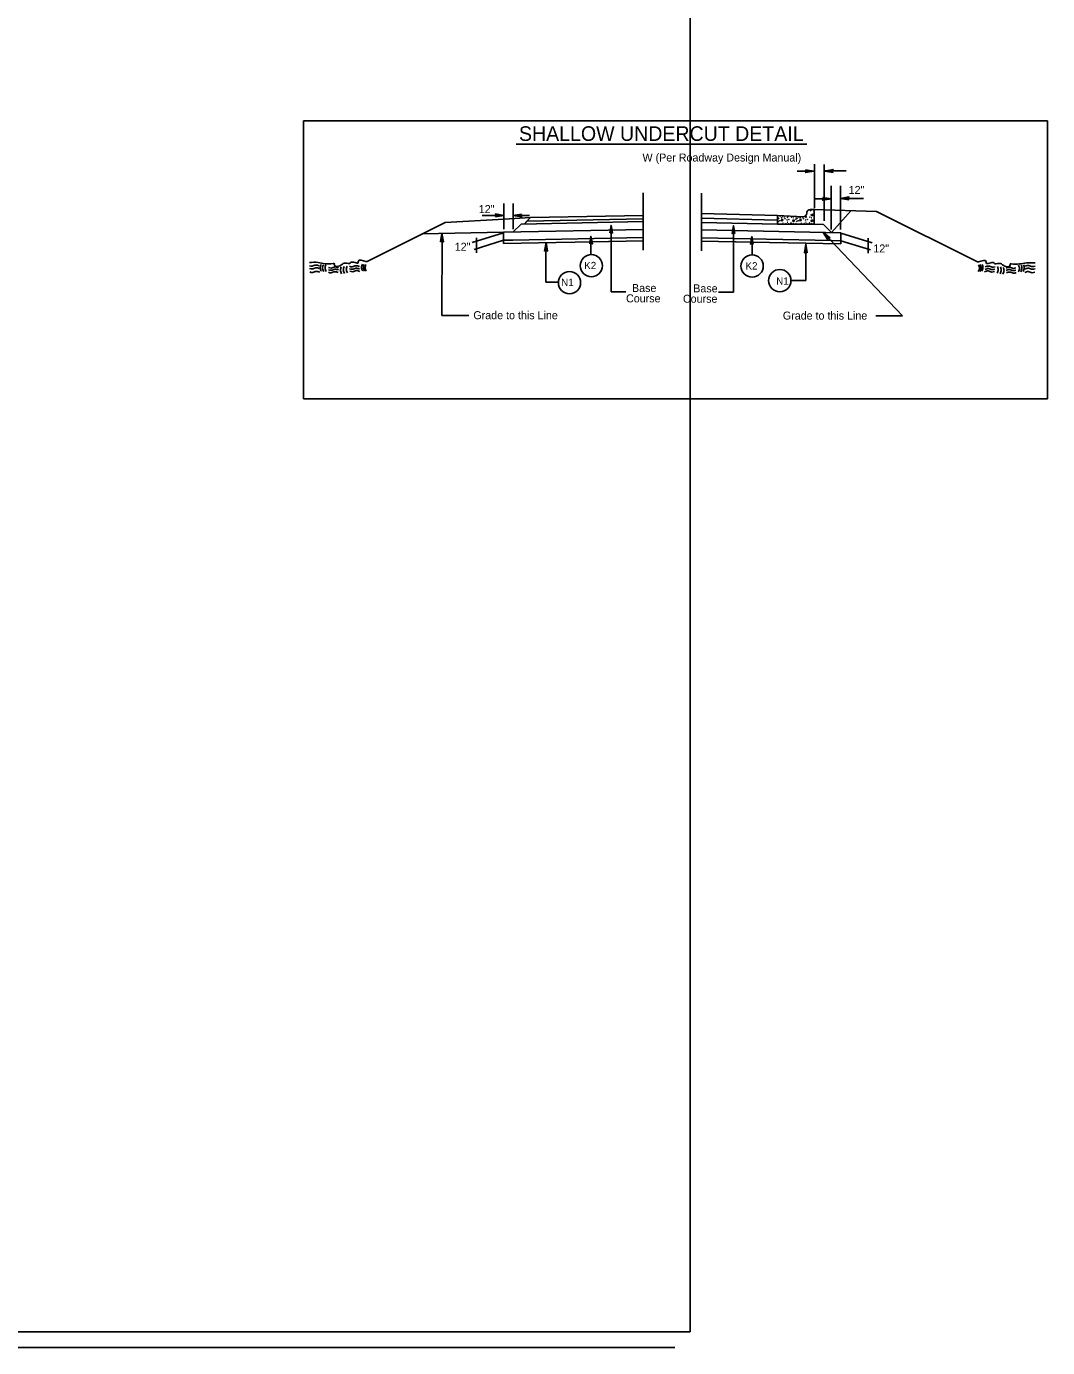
# Model space of a CAD drawing. Extents: x 2294342 to 2294901, y 719427 to 719941.
# Drawn here: x 2294685.4 to 2294852.1, y 719496.2 to 719711.7 of the extents above; entities that cross this region are included whole.
import ezdxf

# ---------------------------------------------------------------- set-up
doc = ezdxf.new("R2010")
doc.units = 0
for name, color, linetype in [('Old_Level_10', 7, 'Continuous'), ('Old_Level_11', 7, 'Continuous'), ('Old_Level_2', 7, 'Continuous'), ('Old_Level_3', 7, 'Continuous'), ('Old_Level_5', 7, 'Continuous'), ('Raster_Level_2', 7, 'Continuous'), ('Sheet Cutting Line CELL', 7, 'Continuous'), ('Sheet Plot Border Outside CELL', 7, 'Continuous'), ('Typical Curb CELL', 7, 'Continuous'), ('Typical Detail Wedge2 CELL', 7, 'Continuous'), ('Typical ID Circle CELL', 7, 'Continuous'), ('Typical Pavement Slope CELL', 7, 'Continuous'), ('Typical Terminator CELL', 7, 'Continuous')]:
    doc.layers.add(name, color=color, linetype=linetype)

msp = doc.modelspace()

# ---------------------------------------------------------------- linework, layer by layer
at = {"layer": 'Old_Level_10'}
for p, q in [((2294741.07, 719673.36), (2294753.83, 719679.75)), ((2294840.68, 719673.31), (2294824.24, 719681.53))]:
    msp.add_line(p, q, dxfattribs=at)
at = {"layer": 'Old_Level_11'}
for p, q in [((2294814.07, 719682.05), (2294814.07, 719689.22)), ((2294815.7, 719679.99), (2294815.7, 719689.2)), ((2294811.29, 719688.12), (2294813.96, 719688.12)), ((2294815.74, 719688.14), (2294819.27, 719688.14)), ((2294786.12, 719675.19), (2294786.12, 719684.57)), ((2294795.63, 719675.13), (2294795.63, 719684.52)), ((2294816.83, 719678.57), (2294816.83, 719685.72)), ((2294818.36, 719678.57), (2294818.36, 719685.73)), ((2294763.39, 719678.62), (2294763.39, 719682.84)), ((2294764.92, 719678.62), (2294764.92, 719682.84)), ((2294814, 719683.61), (2294816.67, 719683.61)), ((2294818.58, 719683.67), (2294822.11, 719683.67)), ((2294763.39, 719680.89), (2294759.86, 719680.89)), ((2294767.59, 719680.89), (2294764.92, 719680.89)), ((2294758.24, 719676.48), (2294763.33, 719678.02)), ((2294823.51, 719676.42), (2294818.42, 719677.97)), ((2294758.54, 719675.34), (2294763.33, 719676.82)), ((2294823.21, 719675.28), (2294818.42, 719676.76))]:
    msp.add_line(p, q, dxfattribs=at)
for points in [[(2294812.64, 719688.33), (2294814.01, 719688.11), (2294812.64, 719687.86), (2294812.82, 719688.11)], [(2294817.12, 719687.9), (2294815.75, 719688.13), (2294817.12, 719688.38), (2294816.95, 719688.13)], [(2294819.72, 719683.43), (2294818.35, 719683.65), (2294819.72, 719683.9), (2294819.54, 719683.65)], [(2294815.44, 719683.83), (2294816.81, 719683.61), (2294815.44, 719683.36), (2294815.61, 719683.61)], [(2294762.02, 719680.66), (2294763.39, 719680.89), (2294762.02, 719681.13), (2294762.19, 719680.89)], [(2294766.29, 719681.11), (2294764.92, 719680.89), (2294766.29, 719680.64), (2294766.12, 719680.89)]]:
    msp.add_lwpolyline(points, close=True, dxfattribs=at)
at = {"layer": 'Old_Level_2'}
for p, q in [((2294824.24, 719681.53), (2294814.03, 719681.85)), ((2294753.83, 719679.75), (2294763.44, 719680.28)), ((2294767.73, 719680.52), (2294766.69, 719679.48)), ((2294816.88, 719678.1), (2294820.06, 719681.66)), ((2294763.33, 719678.13), (2294750.06, 719677.86)), ((2294766.19, 719679.47), (2294764.87, 719678.16)), ((2294815.57, 719679.42), (2294816.88, 719678.1))]:
    msp.add_line(p, q, dxfattribs=at)
for points in [[(2294741.07, 719673.36), (2294740.86, 719673.39), (2294739.61, 719673.39), (2294739.61, 719673.21), (2294738.37, 719673.21), (2294738.19, 719673.03), (2294738.02, 719673.03), (2294737.13, 719673.03), (2294736.95, 719672.86), (2294735.71, 719672.86), (2294735.71, 719673.03), (2294735.53, 719673.03), (2294733.05, 719673.21), (2294731.64, 719673.21)], [(2294840.68, 719673.31), (2294840.89, 719673.33), (2294842.14, 719673.33), (2294842.14, 719673.15), (2294843.38, 719673.15), (2294843.56, 719672.98), (2294843.73, 719672.98), (2294844.62, 719672.98), (2294844.8, 719672.8), (2294846.04, 719672.8), (2294846.04, 719672.98), (2294846.22, 719672.98), (2294848.7, 719673.15), (2294850.12, 719673.15)], [(2294733.24, 719672.64), (2294732.67, 719672.78), (2294732.07, 719672.6), (2294731.64, 719672.68)], [(2294733.26, 719672.2), (2294732.69, 719672.34), (2294732.09, 719672.16), (2294731.66, 719672.24)], [(2294733.32, 719671.62), (2294732.75, 719671.76), (2294732.15, 719671.58), (2294731.71, 719671.66)], [(2294733.55, 719672.86), (2294733.41, 719672.39), (2294733.61, 719671.77)], [(2294733.93, 719672.83), (2294733.79, 719672.35), (2294733.99, 719671.73)], [(2294734.33, 719672.81), (2294734.19, 719672.33), (2294734.39, 719671.71)], [(2294736.34, 719671.56), (2294735.77, 719671.7), (2294735.17, 719671.52), (2294734.74, 719671.6)], [(2294736.38, 719672.34), (2294735.81, 719672.48), (2294735.21, 719672.3), (2294734.77, 719672.38)], [(2294736.38, 719671.98), (2294735.81, 719672.12), (2294735.21, 719671.94), (2294734.77, 719672.02)], [(2294736.85, 719672.47), (2294736.71, 719671.99), (2294736.91, 719671.37)], [(2294737.31, 719672.53), (2294737.17, 719672.05), (2294737.37, 719671.43)], [(2294737.81, 719672.59), (2294737.67, 719672.11), (2294737.86, 719671.49)], [(2294739.8, 719672.54), (2294739.23, 719672.68), (2294738.63, 719672.5), (2294738.19, 719672.58)], [(2294739.82, 719672.14), (2294739.25, 719672.28), (2294738.65, 719672.1), (2294738.21, 719672.18)], [(2294739.88, 719671.74), (2294739.31, 719671.88), (2294738.71, 719671.7), (2294738.27, 719671.78)], [(2294740.29, 719672.92), (2294740.15, 719672.45), (2294740.35, 719671.83)], [(2294740.59, 719672.9), (2294740.45, 719672.43), (2294740.65, 719671.81)], [(2294740.87, 719672.86), (2294740.73, 719672.39), (2294740.92, 719671.77)], [(2294840.88, 719672.81), (2294841.02, 719672.33), (2294840.83, 719671.72)], [(2294841.16, 719672.85), (2294841.3, 719672.37), (2294841.1, 719671.75)], [(2294841.46, 719672.87), (2294841.6, 719672.39), (2294841.4, 719671.77)], [(2294841.87, 719671.69), (2294842.44, 719671.82), (2294843.04, 719671.65), (2294843.48, 719671.73)], [(2294841.93, 719672.08), (2294842.5, 719672.22), (2294843.1, 719672.04), (2294843.54, 719672.12)], [(2294841.95, 719672.48), (2294842.52, 719672.62), (2294843.12, 719672.44), (2294843.56, 719672.52)], [(2294843.95, 719672.53), (2294844.08, 719672.05), (2294843.89, 719671.44)], [(2294844.44, 719672.47), (2294844.58, 719671.99), (2294844.38, 719671.38)], [(2294844.9, 719672.41), (2294845.04, 719671.93), (2294844.84, 719671.32)], [(2294845.37, 719672.28), (2294845.94, 719672.42), (2294846.54, 719672.24), (2294846.98, 719672.32)], [(2294845.37, 719671.92), (2294845.94, 719672.06), (2294846.54, 719671.88), (2294846.98, 719671.96)], [(2294845.41, 719671.51), (2294845.98, 719671.65), (2294846.58, 719671.47), (2294847.02, 719671.55)], [(2294847.42, 719672.75), (2294847.56, 719672.27), (2294847.36, 719671.66)], [(2294847.82, 719672.77), (2294847.96, 719672.29), (2294847.76, 719671.68)], [(2294848.2, 719672.81), (2294848.34, 719672.33), (2294848.14, 719671.72)], [(2294848.43, 719671.57), (2294849, 719671.71), (2294849.6, 719671.53), (2294850.04, 719671.61)], [(2294848.49, 719672.14), (2294849.06, 719672.28), (2294849.66, 719672.1), (2294850.1, 719672.18)], [(2294848.51, 719672.58), (2294849.08, 719672.72), (2294849.68, 719672.54), (2294850.12, 719672.62)]]:
    msp.add_spline(points, degree=3, dxfattribs=at)
at = {"layer": 'Old_Level_3'}
for p, q in [((2294763.44, 719680.28), (2294767.73, 719680.52)), ((2294766.19, 719679.47), (2294786.12, 719679.87)), ((2294767.16, 719679.95), (2294766.69, 719679.48)), ((2294767.73, 719680.52), (2294767.16, 719679.95)), ((2294786.12, 719680.33), (2294767.16, 719679.95)), ((2294767.16, 719679.95), (2294767.16, 719679.95)), ((2294786.12, 719680.89), (2294767.73, 719680.52)), ((2294795.63, 719681.18), (2294808.03, 719680.85)), ((2294795.63, 719680.46), (2294808.01, 719680.13)), ((2294808.03, 719679.45), (2294795.63, 719679.71)), ((2294763.33, 719678.13), (2294786.12, 719678.58)), ((2294763.33, 719678.02), (2294763.33, 719676.82)), ((2294818.42, 719678.07), (2294795.63, 719678.53)), ((2294815.57, 719679.42), (2294814.03, 719679.45)), ((2294818.42, 719677.97), (2294818.42, 719676.76)), ((2294763.33, 719676.82), (2294763.33, 719676.28)), ((2294775.01, 719676.52), (2294775.02, 719676.54)), ((2294775.02, 719676.52), (2294780.46, 719676.63)), ((2294775.02, 719676.54), (2294775.02, 719676.52)), ((2294780.55, 719676.63), (2294786.11, 719676.74)), ((2294786.11, 719676.74), (2294786.11, 719677.28)), ((2294795.64, 719676.68), (2294795.64, 719677.22)), ((2294801.2, 719676.57), (2294795.64, 719676.68)), ((2294806.73, 719676.46), (2294801.29, 719676.57)), ((2294806.73, 719676.48), (2294806.73, 719676.46)), ((2294806.74, 719676.46), (2294806.73, 719676.48)), ((2294818.42, 719676.76), (2294818.42, 719676.23))]:
    msp.add_line(p, q, dxfattribs=at)
for points in [[(2294786.11, 719677.28), (2294764.87, 719676.85), (2294763.33, 719676.82)], [(2294763.33, 719676.28), (2294771.95, 719676.45), (2294775.01, 719676.52)], [(2294780.46, 719676.63), (2294780.55, 719676.63)], [(2294795.64, 719677.22), (2294816.88, 719676.79), (2294818.42, 719676.76)], [(2294801.29, 719676.57), (2294801.2, 719676.57)], [(2294818.42, 719676.23), (2294809.8, 719676.4), (2294806.74, 719676.46)]]:
    msp.add_lwpolyline(points, dxfattribs=at)
at = {"layer": 'Old_Level_5'}
for p, q in [((2294753.27, 719664.56), (2294753.29, 719677.81)), ((2294780.88, 719668.42), (2294780.89, 719679.04)), ((2294800.87, 719668.36), (2294800.86, 719678.98)), ((2294828.48, 719664.5), (2294815.53, 719678.08)), ((2294770.25, 719670), (2294770.26, 719675.83)), ((2294812.69, 719670.25), (2294812.68, 719676.09)), ((2294772.27, 719670), (2294770.25, 719670)), ((2294810.25, 719670.25), (2294812.69, 719670.25)), ((2294783.31, 719668.42), (2294780.88, 719668.42)), ((2294798.44, 719668.36), (2294800.87, 719668.36)), ((2294757.66, 719664.56), (2294753.27, 719664.56)), ((2294824.09, 719664.5), (2294828.48, 719664.5))]:
    msp.add_line(p, q, dxfattribs=at)
at = {"layer": 'Raster_Level_2'}
msp.add_line((2294765.39, 719692.52), (2294812.86, 719692.52), dxfattribs=at)
at = {"layer": 'Sheet Cutting Line CELL'}
msp.add_line((2294454.52, 719496.17), (2294791.32, 719496.17), dxfattribs=at)
at = {"layer": 'Sheet Plot Border Outside CELL'}
msp.add_lwpolyline([(2294793.79, 719718.76), (2294456.99, 719718.76), (2294456.99, 719498.76), (2294793.79, 719498.76)], close=True, dxfattribs=at)
at = {"layer": 'Typical Curb CELL'}
for p, q in [((2294814.03, 719681.85), (2294813.4, 719681.85)), ((2294814.03, 719679.45), (2294814.03, 719681.85)), ((2294808.03, 719679.45), (2294808.03, 719680.85)), ((2294808.03, 719680.85), (2294812.23, 719680.67)), ((2294808.66, 719680.02), (2294808.86, 719680.31)), ((2294808.95, 719680.04), (2294808.66, 719680.02)), ((2294808.86, 719680.31), (2294808.95, 719680.04)), ((2294810.49, 719679.9), (2294810.64, 719680.17)), ((2294810.89, 719679.99), (2294810.49, 719679.9)), ((2294810.64, 719680.17), (2294810.89, 719679.99)), ((2294811.65, 719680.02), (2294811.86, 719680.31)), ((2294811.94, 719680.04), (2294811.65, 719680.02)), ((2294811.86, 719680.31), (2294811.94, 719680.04)), ((2294812.83, 719681.25), (2294812.83, 719681.27)), ((2294813.49, 719679.9), (2294813.64, 719680.17)), ((2294813.89, 719679.99), (2294813.49, 719679.9)), ((2294813.57, 719681.05), (2294813.61, 719680.83)), ((2294813.94, 719680.94), (2294813.57, 719681.05)), ((2294813.61, 719680.83), (2294813.94, 719680.94)), ((2294813.64, 719680.17), (2294813.89, 719679.99)), ((2294814.03, 719679.45), (2294808.03, 719679.45))]:
    msp.add_line(p, q, dxfattribs=at)
for centre in [(2294808.07, 719680.26), (2294808.11, 719680.49), (2294808.21, 719679.91), (2294808.25, 719680.41), (2294808.44, 719680.02), (2294808.51, 719680.71), (2294808.74, 719680.5), (2294808.85, 719680.75), (2294808.94, 719679.62), (2294809.2, 719680.6), (2294809.27, 719680.35), (2294809.44, 719679.57), (2294809.63, 719680.15), (2294809.7, 719680.56), (2294809.71, 719679.78), (2294809.74, 719680.68), (2294809.93, 719680.21), (2294810.27, 719679.65), (2294810.36, 719680.61), (2294810.64, 719680.49), (2294810.68, 719679.56), (2294811.07, 719680.26), (2294811.11, 719680.49), (2294811.2, 719679.91), (2294811.24, 719680.41), (2294811.44, 719680.02), (2294811.5, 719680.63), (2294811.74, 719680.5), (2294811.94, 719679.62), (2294812.2, 719680.6), (2294812.27, 719680.35), (2294812.44, 719679.57), (2294812.63, 719680.15), (2294812.7, 719680.56), (2294812.71, 719679.78), (2294812.74, 719680.68), (2294812.93, 719680.21), (2294813.27, 719679.65), (2294813.35, 719680.61), (2294813.48, 719681.66), (2294813.64, 719680.49), (2294813.68, 719679.56), (2294813.87, 719681.14), (2294814, 719681.58), (2294808.06, 719679.52), (2294808.56, 719679.46), (2294809.85, 719679.5), (2294811.05, 719679.52), (2294811.56, 719679.46), (2294812.85, 719679.5)]:
    msp.add_circle(centre, 0.0192, dxfattribs=at)
for centre, start, end in [((2294813.4, 719681.27), 90, 180), ((2294812.25, 719681.25), 267.6155, 0)]:
    msp.add_arc(centre, 0.575, start, end, dxfattribs=at)
at = {"layer": 'Typical Detail Wedge2 CELL'}
for p, q in [((2294730.69, 719696.29), (2294852.14, 719696.29)), ((2294730.69, 719650.96), (2294730.69, 719696.29)), ((2294852.14, 719696.29), (2294852.14, 719650.96)), ((2294852.14, 719650.96), (2294730.69, 719650.96))]:
    msp.add_line(p, q, dxfattribs=at)
at = {"layer": 'Typical ID Circle CELL'}
for p, q in [((2294777.61, 719674.5), (2294777.61, 719677.29)), ((2294803.91, 719674.43), (2294803.91, 719677.35))]:
    msp.add_line(p, q, dxfattribs=at)
for centre in [(2294777.67, 719672.68), (2294803.91, 719672.63), (2294774.1, 719669.91), (2294808.43, 719670.25)]:
    msp.add_circle(centre, 1.82, dxfattribs=at)
at = {"layer": 'Typical Pavement Slope CELL'}
for p, q in [((2294758.92, 719677.25), (2294758.92, 719674.8)), ((2294822.83, 719677.19), (2294822.83, 719674.75))]:
    msp.add_line(p, q, dxfattribs=at)
for points in [[(2294753.04, 719676.57), (2294753.28, 719677.95), (2294753.53, 719676.56), (2294753.28, 719676.74)], [(2294816.64, 719677.23), (2294815.53, 719678.08), (2294816.29, 719676.89), (2294816.35, 719677.19)], [(2294770.03, 719675.06), (2294770.27, 719676.45), (2294770.52, 719675.06), (2294770.27, 719675.23)], [(2294812.92, 719674.8), (2294812.68, 719676.18), (2294812.44, 719674.79), (2294812.68, 719674.97)]]:
    msp.add_lwpolyline(points, close=True, dxfattribs=at)
at = {"layer": 'Typical Terminator CELL'}
for points in [[(2294777.4, 719676.25), (2294777.61, 719677.48), (2294777.83, 719676.24), (2294777.61, 719676.4)], [(2294780.68, 719678.02), (2294780.89, 719679.25), (2294781.11, 719678.01), (2294780.89, 719678.17)], [(2294801.07, 719677.96), (2294800.86, 719679.19), (2294800.64, 719677.95), (2294800.86, 719678.11)], [(2294804.11, 719676.21), (2294803.89, 719677.44), (2294803.67, 719676.2), (2294803.89, 719676.36)]]:
    msp.add_lwpolyline(points, close=True, dxfattribs=at)

# ---------------------------------------------------------------- texts
at = {"layer": 'Old_Level_3'}
for s, height, p in [('W (Per Roadway Design Manual)', 1.3056, (2294786.02, 719689.68)), ('12"', 1.306, (2294755.37, 719675.12)), ('12"', 1.306, (2294823.7, 719674.84)), ('  Base', 1.306, (2294783.33, 719668.39)), ('  Base', 1.306, (2294793.33, 719668.33)), ('Course', 1.306, (2294783.33, 719666.7)), ('Course', 1.306, (2294792.62, 719666.64)), ('Grade to this Line', 1.3056, (2294758.41, 719663.95)), ('Grade to this Line', 1.3056, (2294808.93, 719663.89))]:
    msp.add_text(s, height=height, dxfattribs=at).set_placement(p)
at = {"layer": 'Old_Level_5'}
for p in [(2294819.67, 719684.39), (2294759.29, 719681.27)]:
    msp.add_text('12"', height=1.306, dxfattribs=at).set_placement(p)
at = {"layer": 'Raster_Level_2'}
msp.add_text('SHALLOW UNDERCUT DETAIL', height=2.3871, rotation=360, dxfattribs=at).set_placement((2294765.85, 719693.04))
at = {"layer": 'Typical Pavement Slope CELL'}
for s, p in [('K2', (2294776.51, 719672.12)), ('K2', (2294802.84, 719672.06)), ('N1', (2294772.75, 719669.36)), ('N1', (2294807.85, 719669.58))]:
    msp.add_text(s, height=1.19, dxfattribs=at).set_placement(p)

doc.saveas('drawing.dxf')
